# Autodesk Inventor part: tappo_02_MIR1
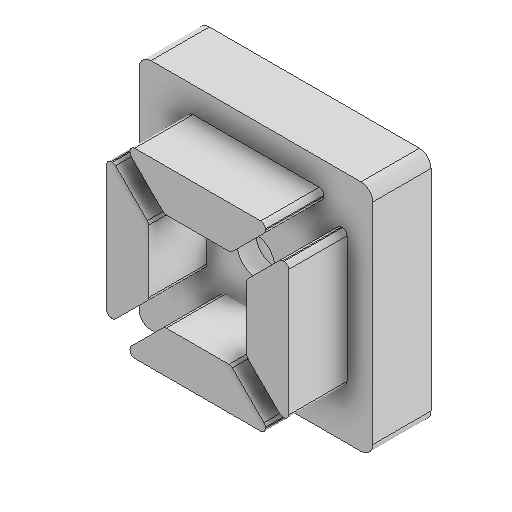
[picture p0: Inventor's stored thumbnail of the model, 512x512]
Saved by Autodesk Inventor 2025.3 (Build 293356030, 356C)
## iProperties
Created: 2026-02
Part Number: tappo_02_MIR1
Material: Generico
Document SubType Name: Modeling
Designer: R5800u
Density: 1 g/cm^3
Appearance: Default
Author: R5800u
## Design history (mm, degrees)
derived "tappo_02.ipt"
  sketch "Schizzo1"
    geometry: L1 (-10, 10)-(10, 10) reference; L2 (10, 10)-(10, -10) reference; L3 (10, -10)-(-10, -10) reference; L4 (-10, -10)-(-10, 10) reference; L5 (-10, 10)-(10, -10) reference; L6 (10, 10)-(-10, -10) reference; L7 (-6, -8)-(-3, -8) reference; L8 (-6, -7.061)-(-6, -8) reference; L9 (-2.939, -4)-(-6, -7.061) reference; L10 (0, 0)-(0, -10) reference; L11 (-2.939, -4)-(0, -4) reference; L12 (-3, -8)-(0, -8) reference; L13 (0, -7.8)-(-3, -7.8) reference; L14 (-3, -7.8)-(-5.8, -7.8) reference; L15 (-5.8, -7.8)-(-5.8, -7.144) reference; L16 (-5.8, -7.144)-(-2.856, -4.2) reference; L17 (-2.856, -4.2)-(0, -4.2) reference; L18 (0, -7.8)-(3, -7.8) reference; L19 (3, -7.8)-(5.8, -7.8) reference; L20 (5.8, -7.8)-(5.8, -7.144) reference; L21 (5.8, -7.144)-(2.856, -4.2) reference; L22 (2.856, -4.2)-(0, -4.2) reference
  sketch "Schizzo2"
    geometry: 1 further point
feature "Solido1::tappo_02.ipt"
feature "Solido2::tappo_02.ipt"
tag "Lavorazione contrassegno1"
node "Solido1"
node "Solido2"
